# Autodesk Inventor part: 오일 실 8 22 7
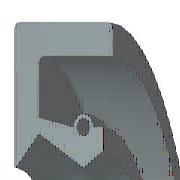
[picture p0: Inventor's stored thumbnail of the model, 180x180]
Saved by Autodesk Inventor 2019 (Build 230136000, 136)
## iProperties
IsCustomPart: 1
Created: 2012-02
Part Number: 오일 실 8 22 7
Material: 고무
Description: 오일-실
Document SubType Name: Modeling
Standard: KS B 2804
Designer: mduedu
Standards Organization: KS
Language: ko-KR
Size Designation: D - 8 22 7
Categories: <MemberInstance><Categories><Category DisplayName="샤프트 부품" InternalName="7f7aeb1f-a693-4053-b835-cee3144e0d98" Mnemonic="SHFT"><Category DisplayName="실링" Intern
Density: 0.93 g/cm^3
Appearance: 고무 - 검은색 - 버전 1.1
Author: mduedu
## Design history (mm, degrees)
revolve "본체" stored, may be unused: angle "d17" = 90 deg
revolve "스프링1" stored, may be unused: angle "d18" = 90 deg
body "Solid1"
sketch "스케치1"
  geometry: L1 (0, 11)-(7, 11); L2 (7, 9.25)-(1.75, 9.25); L3 (1.75, 5.75)-(4.9, 4); L4 (4.9, 4)-(0, 4); L5 (0, 0)-(9.586, 0) reference; L6 (4.9, 4)-(6.3, 4.875); L7 (0, 18)-(0, -3) reference; L8 (-1.941, 0)-(11.507, 0) reference; L9 (4.2, 6.1)-(1.75, 6.59); L10 (1.75, 6.59)-(1.75, 9.25); L11 (0, 11)-(0, 4.088); L12 (4.9, 4)-(0, 4); L13 (1.75, 5.75)-(0.152, 4.028); L14 (7, 11)-(7, 9.25); L15 (5.6, 6.1)-(6.3, 6.1); L16 (6.3, 6.1)-(6.3, 4.875); C1 r 0.455 at (4.9, 6.1); A1 r 0.7 centre (4.9, 6.1) between (5.6, 6.1) and (4.2, 6.1); A2 r 0.088 centre (0.088, 4.088) between (0, 4.088) and (0.152, 4.028); 1 further point
  constraints: 28 end point, 5 horizontal alignment, 5 point on line, 4 point on circle, 4 vertical alignment, 3 centre point, 3 tangent, 2 collinear, 2 horizontal, 2 perpendicular, 1 coincident, 1 parallel
  dimensions: "d0" = 22 diameter of L1 L5 (= SD2); "d1" = 1.75 distance of L1.end L2.start (= SD); "d2" = 0.91 diameter of C1 (= SPDI); "d3" = 1.4 diameter of A1 (= SPDA); "d4" = 8 diameter of L3.end L5 (= NND); "d5" = 11.5 diameter of L3.start L5 (= TKDM); "d7" = 13.18 diameter of L9.end L5 (= TKDM + 0.24 x SWDT); "d8" = 1.75 distance between parallel lines of L11 L10 (= SD); "d9" = 4.9 distance from line of L11 C1.centre (= SPDST); "d10" = 12.2 diameter of C1.centre L5 (= HLDM); "d11" = 0.0875 radius of A2 (= 0.25 x LAB); "d12" = 6.3 distance between parallel lines of L11 L16 (= SDI); "d13" = 9.75 diameter of L6.end L5 (= ABDM); "d14" = 7 distance from line of L11 L1.end (= SWDT)
fillet "모깎기1" dims "d6" = 0.3 (= RR)
other parameters: "SD2" = 22 [user parameter; used in 1 equation term], "SWDT" = 7 [user parameter; used in 2 equation terms], "RR" = 0.3 [user parameter; used in 1 equation term], "SD" = 1.75 [user parameter; used in 2 equation terms], "NND" = 8 [user parameter; used in 1 equation term], "SPDA" = 1.4 [user parameter; used in 1 equation term], "SPDI" = 0.91 [user parameter; used in 1 equation term], "TKDM" = 11.5 [user parameter; used in 2 equation terms], "HLDM" = 12.2 [user parameter; used in 1 equation term], "ABDM" = 9.75 [user parameter; used in 1 equation term], "SDI" = 6.3 [user parameter; used in 1 equation term], "SPDST" = 4.9 [user parameter; used in 1 equation term], "LAB" = 0.35 [user parameter; used in 1 equation term], "d15" = 0, "d16" = 0, "d19" = 0
